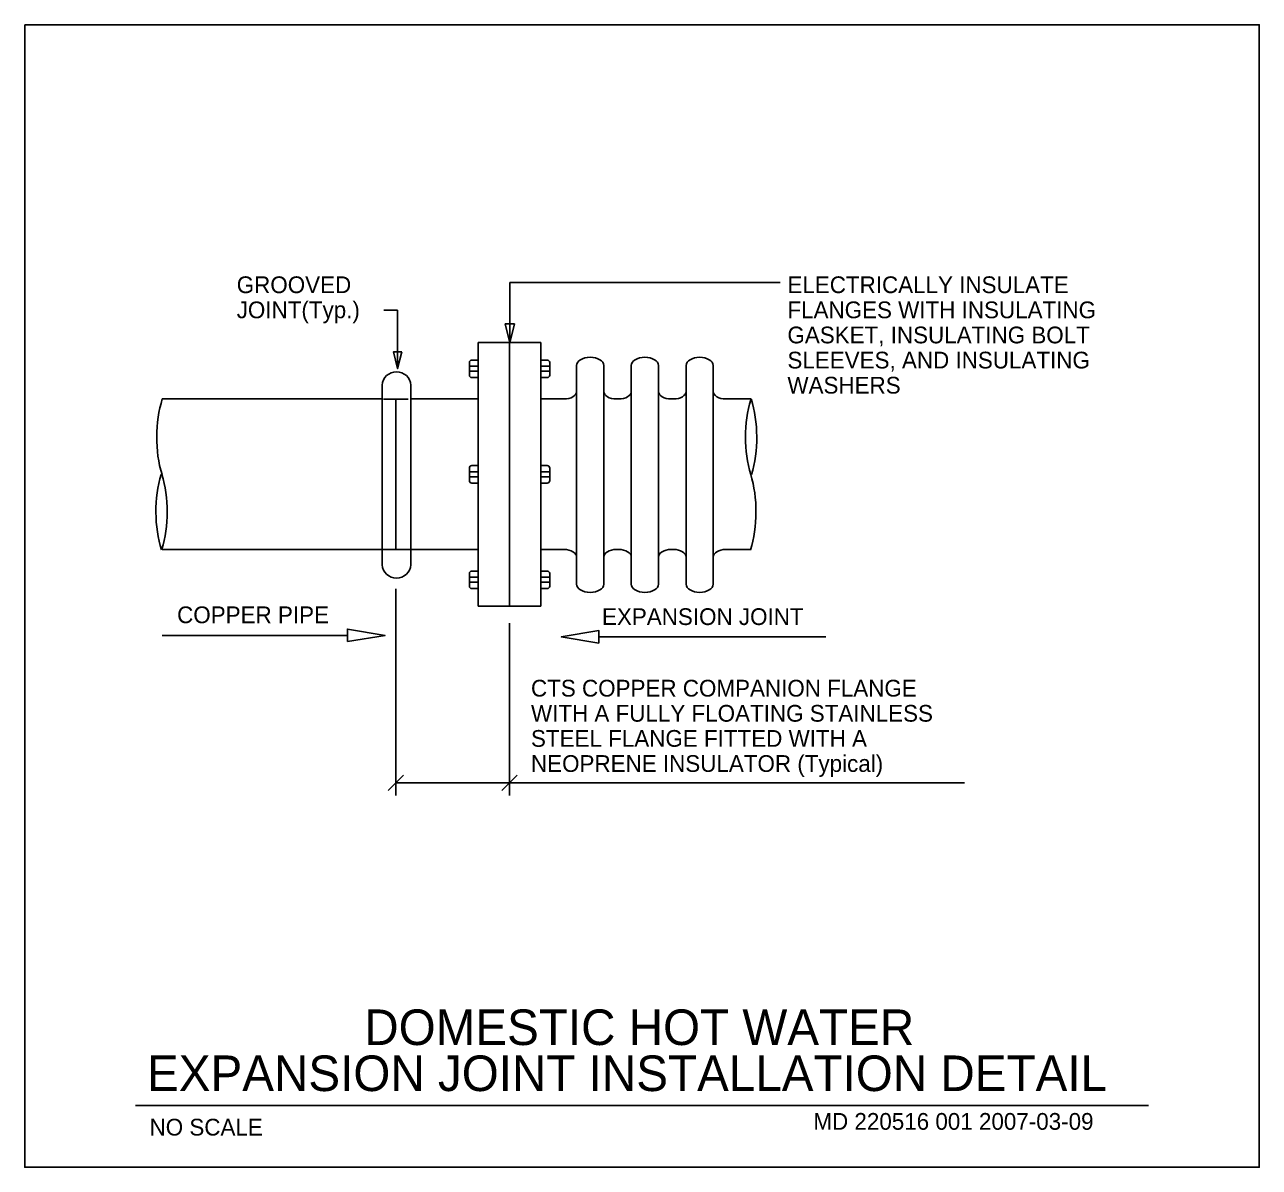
# Model space of a CAD drawing. Extents: x 10054.3 to 10103.5, y 10119.1 to 10164.6.
import ezdxf

# ---------------------------------------------------------------- set-up
doc = ezdxf.new("R2010")
doc.units = 0
for name, color, linetype in [('Default', 7, 'Continuous'), ('G-DETL-GRID', 7, 'Continuous'), ('G-DETL-LINE', 7, 'Continuous')]:
    doc.layers.add(name, color=color, linetype=linetype)

msp = doc.modelspace()

# ---------------------------------------------------------------- linework, layer by layer
at = {"layer": 'Default'}
msp.add_line((10058.731, 10121.509), (10099.047, 10121.509), dxfattribs=at)
at = {"layer": 'G-DETL-GRID'}
msp.add_line((10103.448, 10119.051), (10103.448, 10124.021), dxfattribs=at)
msp.add_lwpolyline([(10054.318, 10164.55), (10103.46, 10164.55), (10103.46, 10119.051), (10054.318, 10119.051)], close=True, dxfattribs=at)
at = {"layer": 'G-DETL-LINE'}
for p, q in [((10073.632, 10154.285), (10084.387, 10154.285)), ((10073.632, 10151.888), (10073.632, 10154.285)), ((10068.618, 10153.179), (10069.163, 10153.179)), ((10069.163, 10150.853), (10069.163, 10153.179)), ((10072.367, 10151.895), (10072.367, 10141.399)), ((10074.866, 10151.895), (10072.367, 10151.895)), ((10072.367, 10151.895), (10072.367, 10141.399)), ((10074.866, 10151.895), (10072.367, 10151.895)), ((10074.866, 10151.895), (10074.866, 10141.399)), ((10072.017, 10151.097), (10072.017, 10150.598)), ((10072.017, 10151.097), (10072.017, 10150.598)), ((10072.017, 10150.948), (10072.367, 10150.948)), ((10072.017, 10150.948), (10072.367, 10150.948)), ((10072.117, 10151.197), (10072.367, 10151.197)), ((10072.117, 10151.197), (10072.367, 10151.197)), ((10075.116, 10151.197), (10074.866, 10151.197)), ((10075.216, 10150.948), (10074.866, 10150.948)), ((10075.216, 10151.097), (10075.216, 10150.598)), ((10076.286, 10150.981), (10076.286, 10142.271)), ((10077.368, 10150.981), (10077.368, 10142.271)), ((10078.464, 10150.981), (10078.464, 10142.271)), ((10079.546, 10150.981), (10079.546, 10142.271)), ((10080.642, 10150.981), (10080.642, 10142.271)), ((10081.725, 10150.981), (10081.725, 10142.271)), ((10072.017, 10150.748), (10072.367, 10150.748)), ((10072.017, 10150.748), (10072.367, 10150.748)), ((10072.117, 10150.498), (10072.367, 10150.498)), ((10072.117, 10150.498), (10072.367, 10150.498)), ((10075.216, 10150.748), (10074.866, 10150.748)), ((10075.116, 10150.498), (10074.866, 10150.498)), ((10068.543, 10143.046), (10068.543, 10150.195)), ((10069.691, 10150.195), (10069.691, 10143.046)), ((10068.543, 10149.646), (10059.795, 10149.646)), ((10068.599, 10149.632), (10069.577, 10149.632)), ((10069.096, 10149.632), (10069.096, 10143.684)), ((10072.367, 10149.646), (10069.691, 10149.646)), ((10074.866, 10149.646), (10075.786, 10149.646)), ((10077.868, 10149.646), (10077.964, 10149.646)), ((10080.046, 10149.646), (10080.142, 10149.646)), ((10082.225, 10149.646), (10082.321, 10149.646)), ((10082.303, 10149.646), (10083.222, 10149.646)), ((10072.017, 10146.897), (10072.017, 10146.397)), ((10072.017, 10146.897), (10072.017, 10146.397)), ((10072.117, 10146.997), (10072.367, 10146.997)), ((10072.117, 10146.997), (10072.367, 10146.997)), ((10075.116, 10146.997), (10074.866, 10146.997)), ((10075.216, 10146.897), (10075.216, 10146.397)), ((10072.017, 10146.747), (10072.367, 10146.747)), ((10072.017, 10146.747), (10072.367, 10146.747)), ((10072.017, 10146.547), (10072.367, 10146.547)), ((10072.017, 10146.547), (10072.367, 10146.547)), ((10075.216, 10146.747), (10074.866, 10146.747)), ((10075.216, 10146.547), (10074.866, 10146.547)), ((10072.117, 10146.297), (10072.367, 10146.297)), ((10072.117, 10146.297), (10072.367, 10146.297)), ((10075.116, 10146.297), (10074.866, 10146.297)), ((10068.543, 10143.648), (10059.795, 10143.648)), ((10068.543, 10143.657), (10069.691, 10143.657)), ((10072.367, 10143.648), (10069.691, 10143.648)), ((10074.866, 10143.648), (10075.848, 10143.648)), ((10077.868, 10143.653), (10077.964, 10143.653)), ((10080.046, 10143.653), (10080.142, 10143.653)), ((10082.178, 10143.648), (10083.22, 10143.648)), ((10082.225, 10143.653), (10082.321, 10143.653)), ((10072.017, 10142.197), (10072.017, 10142.696)), ((10072.017, 10142.197), (10072.017, 10142.696)), ((10072.017, 10142.547), (10072.367, 10142.547)), ((10072.017, 10142.547), (10072.367, 10142.547)), ((10072.117, 10142.796), (10072.367, 10142.796)), ((10072.117, 10142.796), (10072.367, 10142.796)), ((10075.116, 10142.796), (10074.866, 10142.796)), ((10075.216, 10142.547), (10074.866, 10142.547)), ((10075.216, 10142.197), (10075.216, 10142.696)), ((10069.096, 10142.087), (10069.096, 10133.858)), ((10072.017, 10142.347), (10072.367, 10142.347)), ((10072.017, 10142.347), (10072.367, 10142.347)), ((10072.117, 10142.097), (10072.367, 10142.097)), ((10072.117, 10142.097), (10072.367, 10142.097)), ((10075.216, 10142.347), (10074.866, 10142.347)), ((10075.116, 10142.097), (10074.866, 10142.097)), ((10074.866, 10141.399), (10072.367, 10141.399)), ((10074.866, 10141.399), (10072.367, 10141.399)), ((10073.617, 10140.72), (10073.617, 10133.858)), ((10067.166, 10140.234), (10059.795, 10140.234)), ((10077.172, 10140.173), (10086.205, 10140.173)), ((10068.79, 10134.056), (10069.402, 10134.668)), ((10073.311, 10134.056), (10073.922, 10134.668)), ((10069.096, 10134.362), (10091.729, 10134.362))]:
    msp.add_line(p, q, dxfattribs=at)
for points in [[(10073.82, 10152.638), (10073.632, 10151.888), (10073.445, 10152.638)], [(10069.329, 10151.52), (10069.163, 10150.853), (10068.996, 10151.52)], [(10067.166, 10139.984), (10067.166, 10140.484), (10068.665, 10140.234)], [(10077.172, 10139.923), (10077.172, 10140.423), (10075.673, 10140.173)]]:
    msp.add_lwpolyline(points, close=True, dxfattribs=at)
msp.add_lwpolyline([(10073.617, 10151.895), (10073.617, 10141.399)], dxfattribs=at)
msp.add_lwpolyline([(10073.617, 10151.895), (10073.617, 10141.399)], dxfattribs=at)
for centre, radius, start, end in [((10072.117, 10151.097), 0.1, 90, 180), ((10072.117, 10151.097), 0.1, 90, 180), ((10075.116, 10151.097), 0.1, 0, 90), ((10069.117, 10150.154), 0.576, 4.0922, 175.9078), ((10072.117, 10150.598), 0.1, 180, 270), ((10072.117, 10150.598), 0.1, 180, 270), ((10075.116, 10150.598), 0.1, 270, 0), ((10072.117, 10146.897), 0.1, 90, 180), ((10072.117, 10146.897), 0.1, 90, 180), ((10075.116, 10146.897), 0.1, 0, 90), ((10072.117, 10146.397), 0.1, 180, 270), ((10072.117, 10146.397), 0.1, 180, 270), ((10075.116, 10146.397), 0.1, 270, 0), ((10069.117, 10143.087), 0.576, 184.0922, 355.9078), ((10072.117, 10142.696), 0.1, 90, 180), ((10072.117, 10142.696), 0.1, 90, 180), ((10075.116, 10142.696), 0.1, 0, 90), ((10072.117, 10142.197), 0.1, 180, 270), ((10072.117, 10142.197), 0.1, 180, 270), ((10075.116, 10142.197), 0.1, 270, 0)]:
    msp.add_arc(centre, radius, start, end, dxfattribs=at)
for centre, major_axis, ratio, start_param, end_param in [((10076.827, 10150.981), (0.541, 0), 0.6, 0.000053, 3.141593), ((10079.005, 10150.981), (0.541, 0), 0.6, 0.000053, 3.141593), ((10081.184, 10150.981), (0.541, 0), 0.6, 0.000053, 3.141593), ((10075.786, 10149.946), (0.5, 0), 0.6, 4.712389, 6.283185), ((10077.868, 10149.946), (-0.5, 0), 0.6, 0, 1.570796), ((10077.964, 10149.946), (0.5, 0), 0.6, 4.712389, 6.283185), ((10080.046, 10149.946), (-0.5, 0), 0.6, 0, 1.570796), ((10080.142, 10149.946), (0.5, 0), 0.6, 4.712389, 6.283185), ((10082.225, 10149.946), (-0.5, 0), 0.6, 0, 1.570796), ((10060.984, 10148.122), (0, 2.823), 0.5, 1.00072, 2.125194), ((10084.415, 10148.128), (0, -2.823), 0.5, 4.157991, 5.266787), ((10082.045, 10148.128), (0, -2.823), 0.5, 1.016399, 2.138341), ((10060.953, 10145.15), (0, 2.823), 0.5, 1.016399, 2.138341), ((10058.583, 10145.15), (0, 2.823), 0.5, 4.157991, 5.266787), ((10082.015, 10145.156), (0, -2.823), 0.5, 1.00072, 2.125194), ((10075.786, 10143.353), (0.5, 0), 0.6, 0, 1.570796), ((10077.868, 10143.353), (-0.5, 0), 0.6, 4.712389, 6.283185), ((10077.964, 10143.353), (0.5, 0), 0.6, 0, 1.570796), ((10080.046, 10143.353), (-0.5, 0), 0.6, 4.712389, 6.283185), ((10080.142, 10143.353), (0.5, 0), 0.6, 0, 1.570796), ((10082.225, 10143.353), (-0.5, 0), 0.6, 4.712389, 6.283185), ((10076.827, 10142.271), (0.541, 0), 0.6, 3.141593, 6.283132), ((10079.005, 10142.271), (0.541, 0), 0.6, 3.141593, 6.283132), ((10081.184, 10142.271), (0.541, 0), 0.6, 3.141593, 6.283132)]:
    msp.add_ellipse(centre, major_axis=major_axis, ratio=ratio, start_param=start_param, end_param=end_param, dxfattribs=at)

# ---------------------------------------------------------------- texts
at = {"layer": 'Default'}
for s, height, p in [('DOMESTIC HOT WATER', 1.41667, (10067.835, 10123.92)), ('EXPANSION JOINT INSTALLATION DETAIL', 1.41667, (10059.187, 10122.087)), ('NO SCALE', 0.6667, (10059.288, 10120.316)), ('MD 220516 001 2007-03-09', 0.66667, (10085.71, 10120.546))]:
    msp.add_text(s, height=height, dxfattribs=at).set_placement(p)
at = {"layer": 'G-DETL-LINE'}
for s, height, p in [('GROOVED', 0.6667, (10062.757, 10153.861)), ('ELECTRICALLY INSULATE', 0.66667, (10084.677, 10153.861)), ('JOINT(Typ.)', 0.66667, (10062.757, 10152.861)), ('FLANGES WITH INSULATING', 0.66667, (10084.677, 10152.861)), ('GASKET, INSULATING BOLT', 0.66667, (10084.677, 10151.861)), ('SLEEVES, AND INSULATING', 0.66667, (10084.677, 10150.861)), ('WASHERS ', 0.6667, (10084.677, 10149.861)), ('COPPER PIPE', 0.66667, (10060.385, 10140.718)), ('EXPANSION JOINT', 0.66667, (10077.296, 10140.645)), ('CTS COPPER COMPANION FLANGE ', 0.66667, (10074.47, 10137.796)), ('WITH A FULLY FLOATING STAINLESS ', 0.66667, (10074.47, 10136.796)), ('STEEL FLANGE FITTED WITH A ', 0.66667, (10074.47, 10135.796)), ('NEOPRENE INSULATOR (Typical)', 0.66667, (10074.47, 10134.796))]:
    msp.add_text(s, height=height, dxfattribs=at).set_placement(p)

doc.saveas('drawing.dxf')
